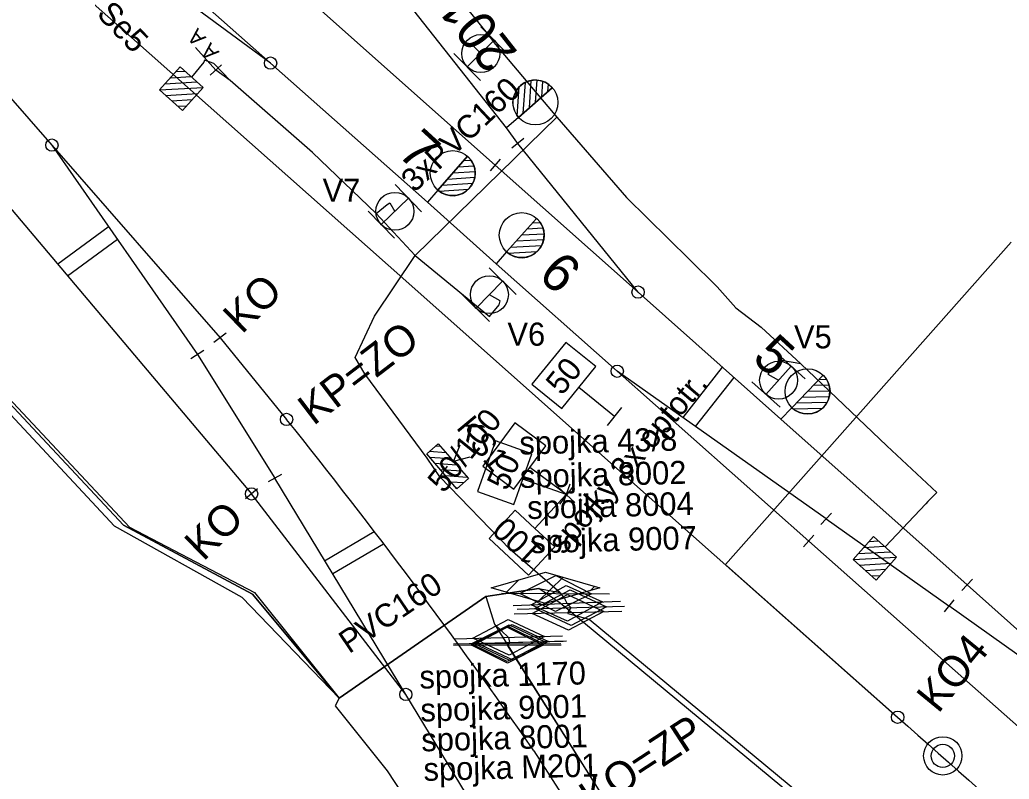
# Model space of a CAD drawing. Extents: x -496570 to -495506, y -1089156 to -1088046.
# Drawn here: x -495875.3 to -495811, y -1088758.8 to -1088709.5 of the extents above; entities that cross this region are included whole.
import ezdxf

# ---------------------------------------------------------------- set-up
doc = ezdxf.new("R2010")
doc.units = 0
for name, color, linetype in [('11', 7, 'Continuous'), ('14', 7, 'Continuous'), ('15', 7, 'Continuous'), ('20', 7, 'Continuous'), ('27', 7, 'Continuous'), ('4', 7, 'Continuous'), ('54', 7, 'Continuous'), ('PŮVODNÍ_NÁVRH', 7, 'Continuous'), ('SEE', 7, 'Continuous')]:
    doc.layers.add(name, color=color, linetype=linetype)

msp = doc.modelspace()

# ---------------------------------------------------------------- linework, layer by layer
at = {"layer": '11'}
for points in [[(-495872.814, -1088725.318), (-495869.527, -1088722.9)], [(-495872.18, -1088726.093), (-495868.935, -1088723.706)], [(-495832.173, -1088735.287), (-495829.621, -1088732.031)], [(-495831.371, -1088735.885), (-495828.872, -1088732.696)], [(-495855.486, -1088744.596), (-495852.248, -1088742.696)], [(-495854.948, -1088745.439), (-495851.641, -1088743.499)]]:
    msp.add_lwpolyline(points, dxfattribs=at)
for radius in [1.246, 0.752]:
    msp.add_circle((-495815.307, -1088757.275), radius, dxfattribs=at)
at = {"layer": '14'}
for p, q in [((-495858.601, -1088706.274), (-495844.395, -1088718.899)), ((-495876.124, -1088721.421), (-495860.222, -1088740.259)), ((-495848.789, -1088721.31), (-495844.334, -1088725.311)), ((-495862.268, -1088730.126), (-495857.943, -1088735.419)), ((-495863.741, -1088731.21), (-495858.708, -1088739.233)), ((-495825.827, -1088735.402), (-495813.723, -1088746.171)), ((-495822.888, -1088741.876), (-495814.907, -1088747.535)), ((-495818.241, -1088754.77), (-495829.337, -1088744.932)), ((-495841.879, -1088756.944), (-495838.553, -1088762.134))]:
    msp.add_line(p, q, dxfattribs=at)
for points in [[(-495842.928, -1088717.493), (-495843.661, -1088716.477), (-495851.703, -1088706.254), (-495860.009, -1088695.696), (-495879.111, -1088671.4), (-495889.727, -1088657.952), (-495895.948, -1088650.027), (-495908.172, -1088634.454), (-495920.247, -1088619.061), (-495937.589, -1088596.936)], [(-495886.163, -1088694.537), (-495878.59, -1088701.24), (-495849.995, -1088726.59), (-495837.458, -1088737.736), (-495818.246, -1088754.776)], [(-495824.02, -1088743.323), (-495815.059, -1088751.264), (-495794.086, -1088769.814), (-495773.102, -1088788.384), (-495756.038, -1088803.462), (-495743.611, -1088814.438)]]:
    msp.add_lwpolyline(points, dxfattribs=at)
for centre in [(-495857.943, -1088735.419), (-495860.222, -1088740.259), (-495818.241, -1088754.77)]:
    msp.add_circle(centre, 0.4, dxfattribs=at)
for centre, major_axis, ratio, start_param, end_param in [((-496157.582, -1088975.75), (384.123, 1.72), 0.999902, 0.601632, 0.671571), ((-493580.338, -1086191.204), (6302.474, -5605.928), 0.403422, 4.716139, 4.719484)]:
    msp.add_ellipse(centre, major_axis=major_axis, ratio=ratio, start_param=start_param, end_param=end_param, dxfattribs=at)
at = {"layer": '15'}
for p, q in [((-495845.322, -1088709.918), (-495843.588, -1088711.668)), ((-495846.205, -1088712.527), (-495844.455, -1088710.793)), ((-495847.072, -1088711.652), (-495845.338, -1088713.402)), ((-495865.491, -1088713.227), (-495864.166, -1088713.149)), ((-495865.139, -1088712.831), (-495864.561, -1088712.797)), ((-495866.197, -1088714.019), (-495863.373, -1088713.855)), ((-495865.844, -1088713.623), (-495863.769, -1088713.502)), ((-495865.801, -1088714.372), (-495863.725, -1088714.251)), ((-495865.404, -1088714.725), (-495864.078, -1088714.647)), ((-495865.008, -1088715.077), (-495864.431, -1088715.043)), ((-495850.886, -1088720.168), (-495849.168, -1088721.934)), ((-495851.793, -1088722.769), (-495850.027, -1088721.051)), ((-495852.652, -1088721.886), (-495850.934, -1088723.652)), ((-495844.788, -1088725.578), (-495843.028, -1088727.302)), ((-495845.632, -1088728.2), (-495843.908, -1088726.44)), ((-495846.512, -1088727.338), (-495844.752, -1088729.062)), ((-495826.076, -1088731.14), (-495824.24, -1088732.784)), ((-495826.802, -1088733.798), (-495825.158, -1088731.962)), ((-495827.72, -1088732.976), (-495825.884, -1088734.62)), ((-495820.079, -1088743.34), (-495819.501, -1088743.307)), ((-495820.785, -1088744.132), (-495818.709, -1088744.013)), ((-495820.431, -1088743.735), (-495819.106, -1088743.659)), ((-495821.137, -1088744.527), (-495818.314, -1088744.366)), ((-495820.742, -1088744.88), (-495818.666, -1088744.761)), ((-495820.346, -1088745.233), (-495819.02, -1088745.157)), ((-495819.95, -1088745.586), (-495819.373, -1088745.553))]:
    msp.add_line(p, q, dxfattribs=at)
for points in [[(-495864.867, -1088712.525), (-495863.373, -1088713.855), (-495864.703, -1088715.349), (-495866.197, -1088714.019)], [(-495864.867, -1088712.525), (-495863.373, -1088713.855), (-495864.703, -1088715.349), (-495866.197, -1088714.019)], [(-495819.806, -1088743.034), (-495818.314, -1088744.366), (-495819.645, -1088745.858), (-495821.137, -1088744.527)], [(-495819.806, -1088743.034), (-495818.314, -1088744.366), (-495819.645, -1088745.858), (-495821.137, -1088744.527)]]:
    msp.add_lwpolyline(points, close=True, dxfattribs=at)
for points in [[(-495864.867, -1088712.525), (-495863.373, -1088713.855), (-495864.703, -1088715.349), (-495866.197, -1088714.019), (-495864.867, -1088712.525)], [(-495864.867, -1088712.525), (-495863.373, -1088713.855), (-495864.703, -1088715.349), (-495866.197, -1088714.019), (-495864.867, -1088712.525)], [(-495819.806, -1088743.034), (-495818.314, -1088744.366), (-495819.645, -1088745.858), (-495821.137, -1088744.527), (-495819.806, -1088743.034)], [(-495819.806, -1088743.034), (-495818.314, -1088744.366), (-495819.645, -1088745.858), (-495821.137, -1088744.527), (-495819.806, -1088743.034)]]:
    msp.add_lwpolyline(points, dxfattribs=at)
for centre in [(-495845.327, -1088711.656), (-495850.907, -1088721.906), (-495844.767, -1088727.316), (-495825.978, -1088732.876)]:
    msp.add_circle(centre, 1.232, dxfattribs=at)
at = {"layer": '20'}
for p, q in [((-495863.864, -1088711.258), (-495862.54, -1088712.73)), ((-495862.912, -1088713.064), (-495862.168, -1088712.396))]:
    msp.add_line(p, q, dxfattribs=at)
at = {"layer": '27'}
for p, q in [((-495858.985, -1088712.277), (-495875.095, -1088700.424)), ((-495842.166, -1088715.173), (-495842.047, -1088713.401)), ((-495841.767, -1088714.823), (-495841.67, -1088713.383)), ((-495842.953, -1088715.712), (-495842.827, -1088713.818)), ((-495840.682, -1088713.874), (-495842.885, -1088715.801)), ((-495842.884, -1088715.802), (-495840.682, -1088713.874)), ((-495842.564, -1088715.523), (-495842.431, -1088713.528)), ((-495841.367, -1088714.474), (-495841.299, -1088713.461)), ((-495840.968, -1088714.124), (-495840.935, -1088713.649)), ((-495842.885, -1088715.802), (-495843.661, -1088716.477)), ((-495842.885, -1088715.801), (-495842.884, -1088715.802)), ((-495842.54, -1088717.178), (-495843.316, -1088717.808)), ((-495873.19, -1088717.6), (-495863.741, -1088731.21)), ((-495835.111, -1088727.15), (-495842.928, -1088717.493)), ((-495848.116, -1088720.532), (-495846.194, -1088718.324)), ((-495846.194, -1088718.324), (-495848.115, -1088720.532)), ((-495844.064, -1088718.524), (-495844.726, -1088719.274)), ((-495846.792, -1088719.011), (-495845.779, -1088718.941)), ((-495846.444, -1088718.611), (-495845.968, -1088718.577)), ((-495847.489, -1088719.811), (-495845.717, -1088719.688)), ((-495847.14, -1088719.411), (-495845.7, -1088719.311)), ((-495848.025, -1088720.6), (-495846.131, -1088720.469)), ((-495847.837, -1088720.211), (-495845.844, -1088720.072)), ((-495848.117, -1088720.532), (-495848.789, -1088721.31)), ((-495848.115, -1088720.532), (-495848.116, -1088720.532)), ((-495843.65, -1088724.543), (-495841.696, -1088722.363)), ((-495841.696, -1088722.363), (-495843.649, -1088724.543)), ((-495842.304, -1088723.042), (-495841.29, -1088722.986)), ((-495841.949, -1088722.646), (-495841.474, -1088722.62)), ((-495842.657, -1088723.436), (-495841.216, -1088723.357)), ((-495843.366, -1088724.226), (-495841.371, -1088724.116)), ((-495843.012, -1088723.831), (-495841.239, -1088723.734)), ((-495829.435, -1088744.846), (-495810.865, -1088723.912)), ((-495843.65, -1088724.543), (-495844.334, -1088725.311)), ((-495843.649, -1088724.543), (-495843.65, -1088724.543)), ((-495843.56, -1088724.612), (-495841.664, -1088724.509)), ((-495861.872, -1088729.821), (-495862.664, -1088730.431)), ((-495863.32, -1088730.941), (-495864.162, -1088731.479)), ((-495822.888, -1088741.876), (-495836.46, -1088732.292)), ((-495825.117, -1088734.658), (-495823.089, -1088732.547)), ((-495823.089, -1088732.547), (-495825.116, -1088734.658)), ((-495823.72, -1088733.204), (-495822.704, -1088733.183)), ((-495823.352, -1088732.821), (-495822.875, -1088732.811)), ((-495824.455, -1088733.969), (-495822.679, -1088733.933)), ((-495824.087, -1088733.586), (-495822.643, -1088733.557)), ((-495824.822, -1088734.351), (-495822.824, -1088734.31)), ((-495825.117, -1088734.658), (-495825.827, -1088735.402)), ((-495825.116, -1088734.658), (-495825.117, -1088734.658)), ((-495825.029, -1088734.73), (-495823.131, -1088734.692)), ((-495858.266, -1088739), (-495859.15, -1088739.466)), ((-495859.837, -1088739.94), (-495860.607, -1088740.578)), ((-495850.196, -1088753.283), (-495860.222, -1088740.259)), ((-495822.548, -1088741.509), (-495823.228, -1088742.243)), ((-495823.69, -1088742.948), (-495824.35, -1088743.698)), ((-495813.384, -1088745.803), (-495814.062, -1088746.539)), ((-495814.597, -1088747.143), (-495815.217, -1088747.927)), ((-495801.447, -1088757.122), (-495814.907, -1088747.535))]:
    msp.add_line(p, q, dxfattribs=at)
for points in [[(-495842.928, -1088717.493), (-495843.661, -1088716.477), (-495851.703, -1088706.254), (-495860.009, -1088695.696)], [(-495873.948, -1088699.018), (-495858.985, -1088712.277), (-495848.789, -1088721.31)], [(-495884.123, -1088705.091), (-495873.19, -1088717.6), (-495862.268, -1088730.126)], [(-495825.827, -1088735.402), (-495835.111, -1088727.15), (-495844.395, -1088718.899)], [(-495844.334, -1088725.311), (-495836.46, -1088732.292), (-495824.02, -1088743.323)], [(-495841.587, -1088767.494), (-495850.196, -1088753.283), (-495858.708, -1088739.233)], [(-495793.346, -1088763.837), (-495801.447, -1088757.122), (-495813.723, -1088746.171)]]:
    msp.add_lwpolyline(points, dxfattribs=at)
for centre, radius in [((-495858.985, -1088712.277), 0.4), ((-495841.778, -1088714.832), 1.462), ((-495873.19, -1088717.6), 0.4), ((-495847.149, -1088719.423), 1.462), ((-495842.666, -1088723.448), 1.462), ((-495835.111, -1088727.15), 0.4), ((-495836.46, -1088732.292), 0.4), ((-495824.096, -1088733.598), 1.462), ((-495850.196, -1088753.283), 0.4)]:
    msp.add_circle(centre, radius, dxfattribs=at)
for centre, start, end in [((-495841.783, -1088714.838), 41.1877, 221.14855), ((-495847.155, -1088719.428), 229.00279, 48.96364), ((-495842.673, -1088723.453), 228.16411, 48.12496), ((-495824.103, -1088733.602), 226.18718, 46.14803)]:
    msp.add_arc(centre, 1.464, start, end, dxfattribs=at)
at = {"layer": '4'}
for p, q in [((-495837.1, -1088735.817), (-495836.156, -1088734.651)), ((-495840.184, -1088740.932), (-495839.29, -1088739.728)), ((-495840.028, -1088741.014), (-495839.522, -1088739.602)), ((-495839.224, -1088740.817), (-495840.326, -1088739.799))]:
    msp.add_line(p, q, dxfattribs=at)
for points in [[(-495836.628, -1088735.234), (-495838.96, -1088733.347), (-495837.859, -1088731.986), (-495839.803, -1088730.414), (-495842.004, -1088733.135), (-495840.061, -1088734.707), (-495838.96, -1088733.347)], [(-495839.737, -1088740.33), (-495842.146, -1088738.543), (-495841.104, -1088737.137), (-495843.112, -1088735.648), (-495845.197, -1088738.459), (-495843.189, -1088739.948), (-495842.146, -1088738.543)], [(-495839.775, -1088740.308), (-495842.6, -1088739.297), (-495842.01, -1088737.65), (-495844.364, -1088736.807), (-495845.543, -1088740.103), (-495843.189, -1088740.945), (-495842.6, -1088739.297)], [(-495839.775, -1088740.308), (-495841.81, -1088742.512), (-495843.096, -1088741.325), (-495844.792, -1088743.161), (-495842.221, -1088745.536), (-495840.525, -1088743.699), (-495841.81, -1088742.512)]]:
    msp.add_lwpolyline(points, dxfattribs=at)
at = {"layer": '54'}
for p, q in [((-495861.61, -1088713.4), (-495862.54, -1088712.73)), ((-495848.253, -1088737.144), (-495847.945, -1088737.165)), ((-495848.652, -1088737.492), (-495847.597, -1088737.565)), ((-495848.659, -1088737.868), (-495847.248, -1088737.965)), ((-495848.311, -1088738.267), (-495846.9, -1088738.365)), ((-495847.98, -1088739.16), (-495847.48, -1088738.46)), ((-495847.963, -1088738.667), (-495846.552, -1088738.764)), ((-495847.614, -1088739.067), (-495846.203, -1088739.164)), ((-495847.266, -1088739.467), (-495846.419, -1088739.525)), ((-495846.918, -1088739.867), (-495846.819, -1088739.873)), ((-495842.789, -1088746.719), (-495840.456, -1088745.567)), ((-495840.456, -1088745.567), (-495838.135, -1088746.743)), ((-495843.953, -1088746.713), (-495836.971, -1088746.749)), ((-495840.468, -1088747.895), (-495842.789, -1088746.719)), ((-495842.059, -1088747.454), (-495839.778, -1088746.203)), ((-495841.986, -1088748.017), (-495839.69, -1088746.793)), ((-495841.808, -1088747.706), (-495839.512, -1088746.482)), ((-495838.135, -1088746.743), (-495840.468, -1088747.895)), ((-495839.778, -1088746.203), (-495837.409, -1088747.278)), ((-495839.69, -1088746.793), (-495837.334, -1088747.897)), ((-495839.512, -1088746.482), (-495837.156, -1088747.586)), ((-495843.223, -1088747.498), (-495836.245, -1088747.234)), ((-495839.69, -1088748.529), (-495842.059, -1088747.454)), ((-495837.409, -1088747.278), (-495839.69, -1088748.529)), ((-495843.15, -1088748.047), (-495836.17, -1088747.867)), ((-495842.972, -1088747.736), (-495835.992, -1088747.556)), ((-495839.63, -1088749.121), (-495841.986, -1088748.017)), ((-495839.452, -1088748.81), (-495841.808, -1088747.706)), ((-495837.334, -1088747.897), (-495839.63, -1088749.121)), ((-495837.156, -1088747.586), (-495839.452, -1088748.81)), ((-495845.843, -1088749.64), (-495843.548, -1088748.415)), ((-495845.786, -1088749.975), (-495843.489, -1088748.754)), ((-495845.583, -1088749.962), (-495843.287, -1088748.738)), ((-495843.548, -1088748.415), (-495841.191, -1088749.518)), ((-495843.489, -1088748.754), (-495841.134, -1088749.861)), ((-495843.287, -1088748.738), (-495840.931, -1088749.842)), ((-495845.942, -1088749.996), (-495843.619, -1088748.824)), ((-495845.929, -1088750.091), (-495843.606, -1088748.92)), ((-495843.619, -1088748.824), (-495841.288, -1088749.98)), ((-495843.606, -1088748.92), (-495841.275, -1088750.077)), ((-495847.106, -1088750), (-495840.124, -1088749.976)), ((-495847.007, -1088749.671), (-495840.027, -1088749.487)), ((-495846.95, -1088750.004), (-495839.97, -1088749.832)), ((-495846.747, -1088749.992), (-495839.767, -1088749.812)), ((-495843.611, -1088751.152), (-495845.942, -1088749.996)), ((-495843.486, -1088750.743), (-495845.843, -1088749.64)), ((-495843.431, -1088751.082), (-495845.786, -1088749.975)), ((-495843.227, -1088751.066), (-495845.583, -1088749.962)), ((-495841.288, -1088749.98), (-495843.611, -1088751.152)), ((-495841.191, -1088749.518), (-495843.486, -1088750.743)), ((-495841.134, -1088749.861), (-495843.431, -1088751.082)), ((-495840.931, -1088749.842), (-495843.227, -1088751.066)), ((-495847.093, -1088750.095), (-495840.111, -1088750.073)), ((-495843.598, -1088751.248), (-495845.929, -1088750.091)), ((-495841.275, -1088750.077), (-495843.598, -1088751.248))]:
    msp.add_line(p, q, dxfattribs=at)
for points in [[(-495969.086, -1088638.597), (-495966.23, -1088641.05), (-495951.776, -1088656.491), (-495936.467, -1088670.11), (-495926.204, -1088679.924), (-495906.892, -1088698.439), (-495894.264, -1088714.786), (-495868.546, -1088742.283), (-495860.148, -1088746.773), (-495854.533, -1088753.524)], [(-495791.286, -1088790.273), (-495804.369, -1088777.872), (-495811.106, -1088771.12), (-495824.244, -1088760.551), (-495840.179, -1088747.357), (-495841.548, -1088746.404), (-495845, -1088746.917), (-495854.533, -1088753.524), (-495860.828, -1088746.983), (-495869.129, -1088742.363), (-495894.734, -1088714.89), (-495907.733, -1088698.276), (-495926.154, -1088680.584), (-495936.743, -1088670.436), (-495952.112, -1088656.757)], [(-495951.647, -1088656.374), (-495945.893, -1088661.488), (-495936.346, -1088669.973), (-495925.773, -1088680.163), (-495906.553, -1088698.536), (-495896.884, -1088711.088), (-495893.995, -1088714.839), (-495868.155, -1088742.416), (-495860.018, -1088746.657), (-495854.533, -1088753.524), (-495845, -1088746.917), (-495841.548, -1088746.404), (-495840.19, -1088746.67), (-495839.894, -1088747.064), (-495839.734, -1088747.366), (-495839.482, -1088747.646), (-495839.66, -1088747.957), (-495839.679, -1088748.032), (-495838.294, -1088748.402), (-495823.909, -1088760.307), (-495810.91, -1088770.79), (-495804.093, -1088777.585), (-495801.02, -1088780.504), (-495790.99, -1088790.03)], [(-495849.29, -1088704.91), (-495844.91, -1088710.36), (-495844.37, -1088711.06), (-495840.39, -1088715.78)], [(-495844.91, -1088710.36), (-495845.72, -1088711.03), (-495845.84, -1088711.14), (-495845.33, -1088711.66)], [(-495849.6, -1088724.78), (-495852.13, -1088722.04), (-495856.26, -1088718.08), (-495861.61, -1088713.4), (-495862.68, -1088712.3), (-495863.28, -1088712.09), (-495863.31, -1088712.22), (-495864.12, -1088713.19)], [(-495840.19, -1088746.67), (-495843.41, -1088743.87), (-495847.98, -1088739.16), (-495848.81, -1088737.93), (-495852.85, -1088732.45), (-495853.48, -1088731.39), (-495852.23, -1088728.72), (-495849.6, -1088724.78), (-495840.39, -1088715.78)], [(-495840.39, -1088715.78), (-495835.86, -1088721), (-495831.77, -1088725.03), (-495829.97, -1088726.8), (-495828.76, -1088728.18), (-495827.12, -1088729.43), (-495824.53, -1088731.81), (-495818.94, -1088737.14), (-495815.69, -1088740.16), (-495816.29, -1088740.75), (-495816.4, -1088740.91), (-495819.06, -1088743.7)], [(-495852.13, -1088722.04), (-495851.41, -1088721.46), (-495851.24, -1088721.36), (-495850.91, -1088721.91)], [(-495849.6, -1088724.78), (-495844.76, -1088728.73), (-495844.13, -1088727.97), (-495844.07, -1088727.71), (-495844.77, -1088727.32)], [(-495824.53, -1088731.81), (-495825.78, -1088731.6), (-495826.68, -1088732.48), (-495825.98, -1088732.88)], [(-495848.088, -1088737.001), (-495846.118, -1088739.263), (-495846.872, -1088739.919), (-495848.842, -1088737.657), (-495848.088, -1088737.001)], [(-495846.677, -1088737.098), (-495847.103, -1088738.132), (-495846.021, -1088737.852)], [(-495845, -1088746.917), (-495844.436, -1088748.714), (-495843.517, -1088749.579), (-495843.46, -1088749.918), (-495843.602, -1088750.084), (-495830.082, -1088771.492), (-495829.77, -1088772.13), (-495829.28, -1088773.41), (-495828.053, -1088775.227), (-495820.013, -1088793.687), (-495819.345, -1088795.504)], [(-495854.533, -1088753.524), (-495854.79, -1088754.03), (-495851.4, -1088758.25), (-495848.28, -1088762.98), (-495845.07, -1088768.22), (-495842.74, -1088771.62), (-495839.22, -1088778.05), (-495838.46, -1088777.74), (-495838.34, -1088777.7), (-495837.01, -1088776.96)]]:
    msp.add_lwpolyline(points, dxfattribs=at)
msp.add_lwpolyline([(-495848.088, -1088737.001), (-495846.118, -1088739.263), (-495846.872, -1088739.919), (-495848.842, -1088737.657)], close=True, dxfattribs=at)
at = {"layer": 'PŮVODNÍ_NÁVRH'}
msp.add_line((-495845, -1088746.917), (-495844.436, -1088748.714), dxfattribs=at)
for points in [[(-495853.48, -1088731.39), (-495852.23, -1088728.72), (-495849.6, -1088724.78), (-495840.39, -1088715.78)], [(-495854.533, -1088753.524), (-495845, -1088746.917), (-495841.548, -1088746.404)], [(-495854.533, -1088753.524), (-495845, -1088746.917), (-495841.548, -1088746.404)]]:
    msp.add_lwpolyline(points, dxfattribs=at)
at = {"layer": 'SEE'}
for p, q in [((-495843.669, -1088746.659), (-495842.87, -1088745.861)), ((-495841.597, -1088747.241), (-495839.998, -1088745.679)), ((-495838.218, -1088746.551), (-495837.926, -1088746.259))]:
    msp.add_line(p, q, dxfattribs=at)
for points in [[(-495845, -1088746.917), (-495854.533, -1088753.524), (-495860.148, -1088746.773), (-495868.546, -1088742.283), (-495894.264, -1088714.786), (-495906.892, -1088698.439), (-495912.357, -1088693.808), (-495926.204, -1088679.924), (-495936.467, -1088670.11), (-495951.776, -1088656.491), (-495966.23, -1088641.05), (-495966.883, -1088640.489), (-495967.344, -1088640.093), (-495969.086, -1088638.597), (-495972.985, -1088642.454), (-495974.115, -1088643.402), (-495975.48, -1088645.263)], [(-495845, -1088746.917), (-495844.436, -1088748.714), (-495831.978, -1088768.541), (-495823.009, -1088786.973)]]:
    msp.add_lwpolyline(points, dxfattribs=at)
msp.add_lwpolyline([(-495844.649, -1088746.369), (-495841.125, -1088745.351), (-495837.601, -1088746.369), (-495841.125, -1088747.387)], close=True, dxfattribs=at)

# ---------------------------------------------------------------- texts
at = {"layer": '14'}
for s, rotation, p in [('KO', 44.42624, (-495860.851, -1088729.926)), ('KP=ZO', 37.35856, (-495856.201, -1088735.866)), ('KO', 44.42624, (-495863.352, -1088744.686)), ('KO4', 50.72946, (-495815.608, -1088754.579)), ('KO=ZP', 33.0552, (-495838.064, -1088761.001))]:
    msp.add_text(s, height=2, rotation=rotation, dxfattribs=at).set_placement(p)
at = {"layer": '15'}
for s, p in [('V7', (-495855.603, -1088721.283)), ('V6', (-495843.595, -1088730.632)), ('V5', (-495824.977, -1088730.805))]:
    msp.add_text(s, height=1.5, dxfattribs=at).set_placement(p)
at = {"layer": '20'}
for s, height, rotation, p in [('Se5', 1.5, 313.62523, (-495870.344, -1088709.134)), ('  A A', 1, 131.96115, (-495861.787, -1088712.111))]:
    msp.add_text(s, height=height, rotation=rotation, dxfattribs=at).set_placement(p)
at = {"layer": '27'}
for s, rotation, p in [('201', 128.19063, (-495842.868, -1088711.586)), ('7', 317.44522, (-495850.826, -1088718.213)), ('6', 317.44522, (-495841.682, -1088726.155)), ('5', 317.44522, (-495827.773, -1088731.528))]:
    msp.add_text(s, height=2.5, rotation=rotation, dxfattribs=at).set_placement(p)
at = {"layer": '4'}
for s, rotation, p in [('50', 51.0203, (-495840.059, -1088733.924)), ('50/100', 51.0203, (-495847.74, -1088740.276)), ('50', 66.14568, (-495843.618, -1088740.121)), ('100', 137.2794, (-495841.207, -1088743.928))]:
    msp.add_text(s, height=1.5, rotation=rotation, dxfattribs=at).set_placement(p)
at = {"layer": '54'}
for s, rotation, p in [('3xPVC160', 43.26601, (-495849.631, -1088720.732)), ('KS1', 309.69732, (-495846.972, -1088735.972)), ('spojka 43/8', 1.47691, (-495842.802, -1088737.706)), ('spojka 8002', 1.47691, (-495842.762, -1088739.877)), ('spojka 8004', 1.47691, (-495842.293, -1088741.894)), ('spojka 9007', 1.47691, (-495842.091, -1088744.118)), ('PVC160', 34.0493, (-495853.885, -1088750.675)), ('spojka 1170', 1.47691, (-495849.295, -1088752.909)), ('spojka 9001', 1.47691, (-495849.231, -1088755.049)), ('spojka 8001', 1.47691, (-495849.173, -1088756.988)), ('spojka M201', 1.47691, (-495849.029, -1088758.904))]:
    msp.add_text(s, height=1.5, rotation=rotation, dxfattribs=at).set_placement(p)
at = {"layer": 'SEE'}
msp.add_text('spojky 3x optotr.', height=1.49999, rotation=49.70919, dxfattribs=at).set_placement((-495839.952, -1088744.261))

doc.saveas('drawing.dxf')
